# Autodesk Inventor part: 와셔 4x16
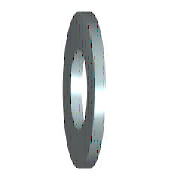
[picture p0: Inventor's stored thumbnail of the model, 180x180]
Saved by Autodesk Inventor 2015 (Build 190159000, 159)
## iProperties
IsCustomPart: 1
Created: 2012-02
Part Number: 와셔 4x16
Material: 강철, 연강
Description: 미터법 평면 와셔
Document SubType Name: Modeling
Standard: ANSI B18.22M
Designer: mduedu
Standard Revision: 1999
Standards Organization: ANSI
Language: ko-KR
Size Designation: 4 W
Categories: <MemberInstance><Categories><Category DisplayName="조임쇠" InternalName="e4da775c-781d-43d5-af7c-5136215cf5a6" Mnemonic="FSTN"><Category DisplayName="와셔" InternalN
Density: 1 g/cm^3
Appearance: 파란색 - 벽 페인트 - 광택
Author: mduedu
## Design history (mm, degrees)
sketch "스케치"
  geometry: C1 r 8 at (0, 0); C2 r 2.35 at (0, 0); 1 further point
  constraints: 2 centre point, 2 coincident
  dimensions: "d0" = 4.7 diameter of C2 (= SD1); "d1" = 16 diameter of C1 (= SD2)
extrude "본체" new body sketch "스케치" distance "d2" = 2.3 (= SD); taper "d3" = 0 deg
workaxis "Work Axis1"
workplane "Work Plane1"
body "Solid1"
other parameters: "SD1" = 4.7 [user parameter; used in 1 equation term], "SD2" = 16 [user parameter; used in 1 equation term], "SD" = 2.3 [user parameter; used in 1 equation term], "d4" = 0, "d5" = 0, "d6" = 0, "d7" = 0, "NND" = 4 [user parameter]
